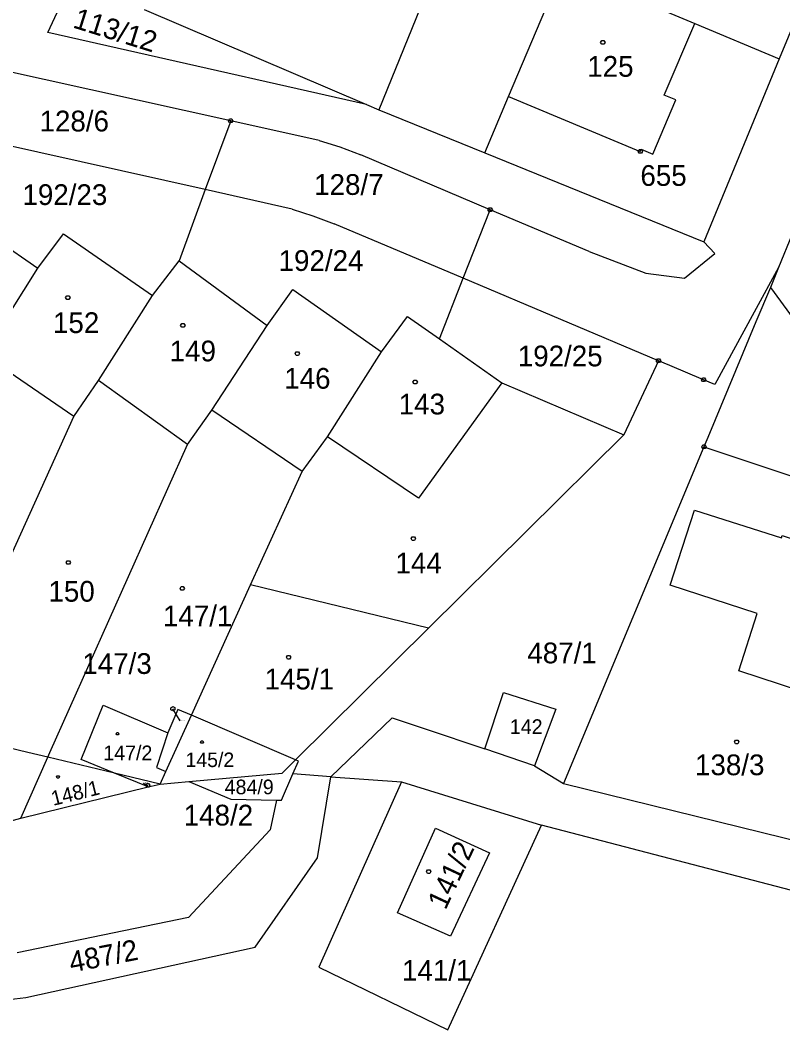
# Model space of a CAD drawing. Extents: x -634640 to -629202, y -1196156 to -1190068.
# Drawn here: x -631329.8 to -631267.3, y -1192911.1 to -1192828.3 of the extents above; entities that cross this region are included whole.
import ezdxf

# ---------------------------------------------------------------- set-up
doc = ezdxf.new("R2010")
doc.units = 0
for name, color, linetype in [('Vrstva 1', 7, 'Continuous'), ('Vrstva 2', 7, 'Continuous'), ('Vrstva 3', 7, 'Continuous'), ('Vrstva 4', 7, 'Continuous'), ('Vrstva 5', 7, 'Continuous'), ('Vrstva 7', 7, 'Continuous'), ('Vrstva 8', 7, 'Continuous')]:
    doc.layers.add(name, color=color, linetype=linetype)

msp = doc.modelspace()

# ---------------------------------------------------------------- linework, layer by layer
at = {"layer": 'Vrstva 1'}
for p, q in [((-631293.39, -1192818.39), (-631300.37, -1192835.66)), ((-631263.19, -1192820.82), (-631267.58, -1192831.48)), ((-631289.75, -1192834.57), (-631285.31, -1192824.07)), ((-631285.31, -1192824.07), (-631274.5, -1192828.59)), ((-631327.48, -1192829.33), (-631325.8, -1192825.72)), ((-631319.61, -1192827.44), (-631301.4, -1192835.22)), ((-631274.5, -1192828.59), (-631267.58, -1192831.48)), ((-631301.4, -1192835.22), (-631327.48, -1192829.33)), ((-631312.51, -1192836.56), (-631336.95, -1192831.15)), ((-631267.58, -1192831.48), (-631273.75, -1192846.48)), ((-631291.69, -1192839.19), (-631289.75, -1192834.57)), ((-631301.4, -1192835.22), (-631300.37, -1192835.66)), ((-631300.37, -1192835.66), (-631291.69, -1192839.19)), ((-631312.51, -1192836.56), (-631314.59, -1192842.21)), ((-631305.25, -1192838.17), (-631312.51, -1192836.56)), ((-631314.59, -1192842.21), (-631338.91, -1192836.76)), ((-631305.25, -1192838.17), (-631303.56, -1192838.71)), ((-631303.56, -1192838.71), (-631301.84, -1192839.37)), ((-631291.26, -1192843.85), (-631301.84, -1192839.37)), ((-631291.69, -1192839.19), (-631273.75, -1192846.48)), ((-631264.19, -1192840.11), (-631267.63, -1192848.59)), ((-631314.59, -1192842.21), (-631316.74, -1192848.05)), ((-631307.48, -1192843.81), (-631314.59, -1192842.21)), ((-631335.61, -1192843.59), (-631328.31, -1192848.64)), ((-631307.48, -1192843.81), (-631305.77, -1192844.36)), ((-631293.47, -1192849.47), (-631291.26, -1192843.85)), ((-631283.15, -1192847.29), (-631291.26, -1192843.85)), ((-631305.77, -1192844.36), (-631304.03, -1192845.01)), ((-631293.47, -1192849.47), (-631304.03, -1192845.01)), ((-631328.31, -1192848.64), (-631326.19, -1192845.82)), ((-631326.19, -1192845.82), (-631318.91, -1192850.88)), ((-631273.75, -1192846.48), (-631272.87, -1192847.44)), ((-631283.15, -1192847.29), (-631278.52, -1192849.04)), ((-631318.91, -1192850.88), (-631316.74, -1192848.05)), ((-631316.74, -1192848.05), (-631309.51, -1192853.33)), ((-631275.35, -1192849.45), (-631272.87, -1192847.44)), ((-631332.76, -1192855.73), (-631328.31, -1192848.64)), ((-631267.63, -1192848.59), (-631269.63, -1192852.26)), ((-631267.63, -1192848.59), (-631268.31, -1192850.22)), ((-631295.42, -1192854.44), (-631293.47, -1192849.47)), ((-631277.47, -1192856.23), (-631293.47, -1192849.47)), ((-631278.52, -1192849.04), (-631275.35, -1192849.45)), ((-631309.51, -1192853.33), (-631307.43, -1192850.39)), ((-631307.43, -1192850.39), (-631300.16, -1192855.5)), ((-631268.31, -1192850.22), (-631269.49, -1192853.05)), ((-631268.31, -1192850.22), (-631262.93, -1192857.61)), ((-631323.34, -1192857.84), (-631318.91, -1192850.88)), ((-631269.63, -1192852.26), (-631272.86, -1192858.17)), ((-631300.16, -1192855.5), (-631298.04, -1192852.61)), ((-631298.04, -1192852.61), (-631295.42, -1192854.44)), ((-631269.49, -1192853.05), (-631273.44, -1192862.53)), ((-631314.05, -1192860.28), (-631309.51, -1192853.33)), ((-631295.42, -1192854.44), (-631290.3, -1192858.03)), ((-631304.59, -1192862.47), (-631300.16, -1192855.5)), ((-631325.37, -1192860.81), (-631332.76, -1192855.73)), ((-631277.47, -1192856.23), (-631280.32, -1192862.29)), ((-631276.55, -1192856.62), (-631277.47, -1192856.23)), ((-631273.78, -1192857.78), (-631276.55, -1192856.62)), ((-631325.37, -1192860.81), (-631323.34, -1192857.84)), ((-631316.06, -1192863.08), (-631323.34, -1192857.84)), ((-631290.3, -1192858.03), (-631297.14, -1192867.48)), ((-631290.3, -1192858.03), (-631280.32, -1192862.29)), ((-631272.86, -1192858.17), (-631273.78, -1192857.78)), ((-631316.06, -1192863.08), (-631314.05, -1192860.28)), ((-631306.66, -1192865.3), (-631314.05, -1192860.28)), ((-631336.95, -1192886.45), (-631325.37, -1192860.81)), ((-631306.66, -1192865.3), (-631304.59, -1192862.47)), ((-631297.14, -1192867.48), (-631304.59, -1192862.47)), ((-631280.32, -1192862.29), (-631296.31, -1192878.13)), ((-631273.44, -1192862.53), (-631273.75, -1192863.28)), ((-631327.31, -1192888.34), (-631316.06, -1192863.08)), ((-631273.75, -1192863.28), (-631285.25, -1192890.88)), ((-631273.75, -1192863.28), (-631250.78, -1192870.94)), ((-631310.88, -1192874.59), (-631306.66, -1192865.3)), ((-631315.73, -1192885.28), (-631310.88, -1192874.59)), ((-631296.31, -1192878.13), (-631310.88, -1192874.59)), ((-631296.31, -1192878.13), (-631307.2, -1192888.92)), ((-631291.7, -1192888.04), (-631290.17, -1192883.4)), ((-631290.17, -1192883.4), (-631285.88, -1192884.79)), ((-631324.75, -1192888.91), (-631322.96, -1192884.44)), ((-631322.96, -1192884.44), (-631317.65, -1192886.71)), ((-631317.83, -1192889.89), (-631315.73, -1192885.28)), ((-631316.84, -1192884.81), (-631317.65, -1192886.71)), ((-631315.73, -1192885.28), (-631316.84, -1192884.81)), ((-631307.2, -1192888.92), (-631315.73, -1192885.28)), ((-631285.88, -1192884.79), (-631287.63, -1192889.41)), ((-631304.31, -1192890.31), (-631299.28, -1192885.49)), ((-631299.28, -1192885.49), (-631296.59, -1192886.39)), ((-631329.13, -1192888.32), (-631336.95, -1192886.45)), ((-631317.65, -1192886.71), (-631318.59, -1192889.57)), ((-631296.59, -1192886.39), (-631291.7, -1192888.04)), ((-631327.48, -1192888.72), (-631329.13, -1192888.32)), ((-631327.48, -1192888.72), (-631327.31, -1192888.34)), ((-631287.63, -1192889.41), (-631291.7, -1192888.04)), ((-631329.7, -1192893.71), (-631327.48, -1192888.72)), ((-631322.02, -1192890.02), (-631327.48, -1192888.72)), ((-631322.02, -1192890.02), (-631324.75, -1192888.91)), ((-631307.2, -1192888.92), (-631308.3, -1192890.01)), ((-631307.41, -1192890.08), (-631306.96, -1192889.03)), ((-631306.96, -1192889.03), (-631307.2, -1192888.92)), ((-631287.63, -1192889.41), (-631285.25, -1192890.88)), ((-631319.08, -1192890.72), (-631322.02, -1192890.02)), ((-631319.26, -1192891.15), (-631322.02, -1192890.02)), ((-631318.59, -1192889.57), (-631317.83, -1192889.89)), ((-631318.29, -1192890.91), (-631317.83, -1192889.89)), ((-631315.93, -1192890.7), (-631308.3, -1192890.01)), ((-631308.34, -1192892.24), (-631307.41, -1192890.08)), ((-631304.31, -1192890.31), (-631307.41, -1192890.08)), ((-631305.4, -1192896.96), (-631304.31, -1192890.31)), ((-631304.31, -1192890.31), (-631298.53, -1192890.73)), ((-631329.7, -1192893.71), (-631319.26, -1192891.15)), ((-631319.26, -1192891.15), (-631318.29, -1192890.91)), ((-631318.29, -1192890.91), (-631319.08, -1192890.72)), ((-631318.29, -1192890.91), (-631315.93, -1192890.7)), ((-631315.93, -1192890.7), (-631312.49, -1192892.16)), ((-631298.53, -1192890.73), (-631305.28, -1192905.91)), ((-631298.53, -1192890.73), (-631287.05, -1192894.28)), ((-631285.25, -1192890.88), (-631260.27, -1192897.02)), ((-631312.49, -1192892.16), (-631308.76, -1192892.23)), ((-631308.76, -1192892.23), (-631309.27, -1192894.67)), ((-631308.76, -1192892.23), (-631308.34, -1192892.24)), ((-631333.21, -1192894.65), (-631329.7, -1192893.71)), ((-631294.72, -1192911.05), (-631287.05, -1192894.28)), ((-631251.75, -1192903.51), (-631287.05, -1192894.28)), ((-631309.27, -1192894.67), (-631315.97, -1192901.85)), ((-631298.84, -1192901.46), (-631295.74, -1192894.53)), ((-631295.74, -1192894.53), (-631291.3, -1192896.54)), ((-631310.5, -1192904.28), (-631305.4, -1192896.96)), ((-631291.3, -1192896.54), (-631294.5, -1192903.38)), ((-631315.97, -1192901.85), (-631329.99, -1192904.74)), ((-631294.5, -1192903.38), (-631298.84, -1192901.46)), ((-631329.28, -1192908.41), (-631310.5, -1192904.28)), ((-631305.28, -1192905.91), (-631294.72, -1192911.05)), ((-631346.99, -1192910.33), (-631329.28, -1192908.41))]:
    msp.add_line(p, q, dxfattribs=at)
msp.add_lwpolyline([(-631274.53, -1192868.46), (-631267.39, -1192870.73), (-631267.33, -1192870.54), (-631255.28, -1192874.49), (-631258.9, -1192885.58), (-631270.88, -1192881.64), (-631269.4, -1192876.94), (-631276.51, -1192874.62), (-631274.53, -1192868.46)], dxfattribs=at)
at = {"layer": 'Vrstva 3'}
for points in [[(-631297.46, -1192870.65), (-631297.37, -1192870.8), (-631297.46, -1192870.95), (-631297.64, -1192870.95), (-631297.73, -1192870.8), (-631297.64, -1192870.65), (-631297.46, -1192870.65)], [(-631325.71, -1192872.61), (-631325.62, -1192872.76), (-631325.71, -1192872.91), (-631325.89, -1192872.91), (-631325.98, -1192872.76), (-631325.89, -1192872.61), (-631325.71, -1192872.61)], [(-631316.39, -1192874.73), (-631316.3, -1192874.88), (-631316.39, -1192875.03), (-631316.57, -1192875.03), (-631316.66, -1192874.88), (-631316.57, -1192874.73), (-631316.39, -1192874.73)], [(-631307.68, -1192880.38), (-631307.59, -1192880.53), (-631307.68, -1192880.68), (-631307.86, -1192880.68), (-631307.95, -1192880.53), (-631307.86, -1192880.38), (-631307.68, -1192880.38)], [(-631321.72, -1192886.69), (-631321.659, -1192886.79), (-631321.72, -1192886.89), (-631321.84, -1192886.89), (-631321.901, -1192886.79), (-631321.84, -1192886.69), (-631321.72, -1192886.69)], [(-631314.8, -1192887.37), (-631314.739, -1192887.47), (-631314.8, -1192887.57), (-631314.92, -1192887.57), (-631314.981, -1192887.47), (-631314.92, -1192887.37), (-631314.8, -1192887.37)], [(-631270.98, -1192887.31), (-631270.89, -1192887.46), (-631270.98, -1192887.61), (-631271.16, -1192887.61), (-631271.25, -1192887.46), (-631271.16, -1192887.31), (-631270.98, -1192887.31)], [(-631326.59, -1192890.23), (-631326.529, -1192890.33), (-631326.59, -1192890.43), (-631326.71, -1192890.43), (-631326.771, -1192890.33), (-631326.71, -1192890.23), (-631326.59, -1192890.23)]]:
    msp.add_lwpolyline(points, dxfattribs=at)
at = {"layer": 'Vrstva 4'}
for p, q in [((-631277, -1192834.46), (-631274.5, -1192828.59)), ((-631289.75, -1192834.57), (-631278.96, -1192839.08)), ((-631277.94, -1192839.29), (-631276.06, -1192834.86)), ((-631276.06, -1192834.86), (-631277, -1192834.46)), ((-631278.96, -1192839.08), (-631278.88, -1192838.89)), ((-631278.88, -1192838.89), (-631277.94, -1192839.29))]:
    msp.add_line(p, q, dxfattribs=at)
at = {"layer": 'Vrstva 5'}
for points in [[(-631281.94, -1192830), (-631281.85, -1192830.15), (-631281.94, -1192830.3), (-631282.12, -1192830.3), (-631282.21, -1192830.15), (-631282.12, -1192830), (-631281.94, -1192830)], [(-631325.76, -1192850.91), (-631325.67, -1192851.06), (-631325.76, -1192851.21), (-631325.94, -1192851.21), (-631326.03, -1192851.06), (-631325.94, -1192850.91), (-631325.76, -1192850.91)], [(-631316.34, -1192853.19), (-631316.25, -1192853.34), (-631316.34, -1192853.49), (-631316.52, -1192853.49), (-631316.61, -1192853.34), (-631316.52, -1192853.19), (-631316.34, -1192853.19)], [(-631306.96, -1192855.49), (-631306.87, -1192855.64), (-631306.96, -1192855.79), (-631307.14, -1192855.79), (-631307.23, -1192855.64), (-631307.14, -1192855.49), (-631306.96, -1192855.49)], [(-631297.31, -1192857.83), (-631297.22, -1192857.98), (-631297.31, -1192858.13), (-631297.49, -1192858.13), (-631297.58, -1192857.98), (-631297.49, -1192857.83), (-631297.31, -1192857.83)], [(-631296.2, -1192897.94), (-631296.11, -1192898.09), (-631296.2, -1192898.24), (-631296.38, -1192898.24), (-631296.47, -1192898.09), (-631296.38, -1192897.94), (-631296.2, -1192897.94)]]:
    msp.add_lwpolyline(points, dxfattribs=at)
at = {"layer": 'Vrstva 7'}
for p, q in [((-631316.65, -1192885.74), (-631317.25, -1192884.74)), ((-631319.68, -1192890.85), (-631319.3, -1192891.02))]:
    msp.add_line(p, q, dxfattribs=at)
for points in [[(-631317.25, -1192884.565), (-631317.096, -1192884.647), (-631317.096, -1192884.822), (-631317.25, -1192884.915), (-631317.404, -1192884.833), (-631317.404, -1192884.658), (-631317.25, -1192884.565)], [(-631319.198, -1192891.162), (-631319.371, -1192891.185), (-631319.473, -1192891.043), (-631319.402, -1192890.878), (-631319.229, -1192890.855), (-631319.127, -1192890.997), (-631319.198, -1192891.162)]]:
    msp.add_lwpolyline(points, dxfattribs=at)
at = {"layer": 'Vrstva 8'}
for points in [[(-631312.42, -1192836.41), (-631312.33, -1192836.56), (-631312.42, -1192836.71), (-631312.6, -1192836.71), (-631312.69, -1192836.56), (-631312.6, -1192836.41), (-631312.42, -1192836.41)], [(-631278.87, -1192838.93), (-631278.78, -1192839.08), (-631278.87, -1192839.23), (-631279.05, -1192839.23), (-631279.14, -1192839.08), (-631279.05, -1192838.93), (-631278.87, -1192838.93)], [(-631291.17, -1192843.7), (-631291.08, -1192843.85), (-631291.17, -1192844), (-631291.35, -1192844), (-631291.44, -1192843.85), (-631291.35, -1192843.7), (-631291.17, -1192843.7)], [(-631277.38, -1192856.08), (-631277.29, -1192856.23), (-631277.38, -1192856.38), (-631277.56, -1192856.38), (-631277.65, -1192856.23), (-631277.56, -1192856.08), (-631277.38, -1192856.08)], [(-631273.69, -1192857.63), (-631273.6, -1192857.78), (-631273.69, -1192857.93), (-631273.87, -1192857.93), (-631273.96, -1192857.78), (-631273.87, -1192857.63), (-631273.69, -1192857.63)], [(-631273.66, -1192863.13), (-631273.57, -1192863.28), (-631273.66, -1192863.43), (-631273.84, -1192863.43), (-631273.93, -1192863.28), (-631273.84, -1192863.13), (-631273.66, -1192863.13)]]:
    msp.add_lwpolyline(points, dxfattribs=at)

# ---------------------------------------------------------------- texts
at = {"layer": 'Vrstva 2'}
for s, height, rotation, p in [('113/12', 1.7, 342.62876, (-631325.515, -1192828.907)), ('148/1', 1.2, 13.86558, (-631327.051, -1192892.704)), ('141/2', 1.7, 64.91612, (-631294.914, -1192901.294)), ('487/2', 1.7, 10.94349, (-631325.567, -1192906.365))]:
    msp.add_text(s, height=height, rotation=rotation, dxfattribs=at).set_placement(p)
for s, height, p in [('125', 1.7, (-631283.307, -1192832.96)), ('128/6', 1.7, (-631328.167, -1192837.44)), ('128/7', 1.7, (-631305.677, -1192842.64)), ('192/23', 1.7, (-631329.567, -1192843.47)), ('192/24', 1.7, (-631308.587, -1192848.87)), ('152', 1.7, (-631327.067, -1192853.96)), ('149', 1.7, (-631317.507, -1192856.28)), ('192/25', 1.7, (-631288.997, -1192856.69)), ('146', 1.7, (-631308.127, -1192858.52)), ('143', 1.7, (-631298.747, -1192860.63)), ('144', 1.7, (-631299.017, -1192873.66)), ('150', 1.7, (-631327.437, -1192875.97)), ('147/1', 1.7, (-631318.057, -1192877.99)), ('487/1', 1.7, (-631288.213, -1192881.02)), ('145/1', 1.7, (-631309.737, -1192883.16)), ('147/3', 0.1, (-631316.627, -1192885.74)), ('142', 1.2, (-631289.643, -1192886.81)), ('147/2', 1.2, (-631322.943, -1192888.96)), ('145/2', 1.19, (-631316.205, -1192889.52)), ('138/3', 1.7, (-631274.48, -1192890.19)), ('148/2', 0.1, (-631319.657, -1192890.85)), ('484/9', 1.2, (-631313.002, -1192891.75)), ('141/1', 1.7, (-631298.477, -1192907.03))]:
    msp.add_text(s, height=height, dxfattribs=at).set_placement(p)
at = {"layer": 'Vrstva 7'}
for s, p in [('147/3', (-631324.662, -1192881.89)), ('148/2', (-631316.357, -1192894.31))]:
    msp.add_text(s, height=1.7, dxfattribs=at).set_placement(p)
at = {"layer": 'Vrstva 8'}
msp.add_text('655', height=1.7, dxfattribs=at).set_placement((-631278.953, -1192841.9))

doc.saveas('drawing.dxf')
